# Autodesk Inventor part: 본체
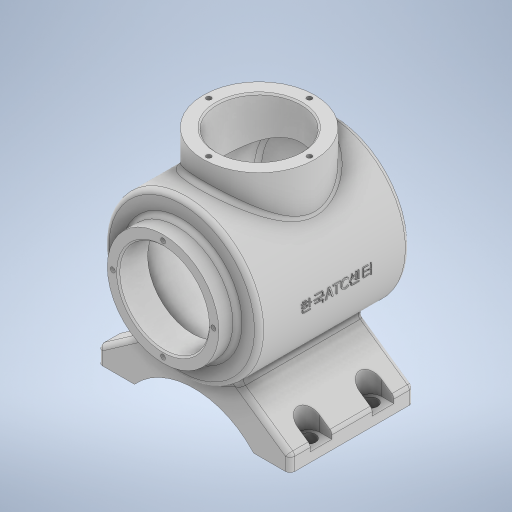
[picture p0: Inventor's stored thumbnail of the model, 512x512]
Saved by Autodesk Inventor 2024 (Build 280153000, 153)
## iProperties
Created: 2023-08
Part Number: 본체
Material: 일반
Document SubType Name: Modeling
Designer: Owner
Density: 1 g/cm^3
Appearance: 기본값
Mass: 474.432 g
Surface Area: 1056.17 cm^2
Volume: 474.432 cm^3
Author: Owner
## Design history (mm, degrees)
sketch "스케치1"
  geometry: L1 (0, 60)-(0, -60); L2 (0, -60)-(0, -8.872); L3 (29, 60)-(36, 60); L4 (36, 60)-(36, 48); L5 (36, 48)-(50, 48); L6 (50, 48)-(50, -48.336); L7 (43, -43.887)-(43, 41); L8 (43, 41)-(29, 41); L9 (29, 41)-(29, 60); A1 r 113 centre (0, 53) between (0, -60) and (50, -48.336); A2 r 106 centre (0, 53) between (0, -53) and (43, -43.887); 2 further points
  constraints: 18 end point, 4 perpendicular, 4 point on circle, 2 centre point, 2 point on line, 2 vertical, 1 coincident, 1 horizontal, 1 horizontal alignment, 1 midpoint, 1 vertical alignment, 2 other
  dimensions: "d1" = 120 distance of L1.start L1.end; "d2" = 113 radius of A1; "d3" = 100 diameter of L6 L1; "d4" = 72 diameter of L4 L1; "d5" = 12 distance of L3.end L4.end; "d6" = 7 radial gap between concentric circles of A1 A2; "d7" = 86 diameter of L7 L1; "d80" = 19 distance of L8.end L3.start (derived)
revolve "회전1" sketch "스케치1" stored, may be unused: angle "d8" = 90 deg
fillet "모깎기1" dims "d9" = 3
node "작업 평면1"
sketch "스케치2"
  geometry: L1 (-36, 60)-(36, 60) reference; C1 r 36 at (0, -2); 1 further point
  constraints: 1 centre point, 1 vertical alignment
  dimensions: "d11" = 72 diameter of C1; "d12" = 62 distance from line of L1 C1.centre
extrude "돌출1" join sketch "스케치2" stored distance "d13" = 10; taper "d14" = 0 deg
sketch "스케치3"
  geometry: L1 (36, -62)-(-36, -62) reference; C1 r 36 at (0, 0) reference; 2 further points
  dimensions: "d15" = 62 distance from line of L1 point (-32.5, 0); "d16" = 32.5 distance of C1.centre point (-32.5, 0)
hole "구멍1" sketch "스케치3" at (-32.5, 0) diameter "d17" = 3.242; stored, may be unused: countersink angle "d21" = 90 deg, drill point angle "d23" = 118 deg; dims "d18" = 8, "d19" = 4, "d20" = 2, "d22" = 10
sketch "스케치4"
  geometry: C1 r 36 at (0, 0) reference; 2 further points
  constraints: 1 coincident
hole "구멍2" sketch "스케치4" at (0, 0) diameter "d24" = 54; stored, may be unused: countersink angle "d28" = 90 deg, drill point angle "d30" = 0 deg; dims "d25" = 8, "d26" = 4, "d27" = 2, "d29" = 10
chamfer "모따기1" distance "d34" = 1; stored, may be unused: second distance "d35" = 2, angle "d36" = 45 deg
fillet "모깎기2" dims "d37" = 3
sketch "스케치5"
  geometry: L1 (-62, -77)-(-62, -67); L2 (62, -77)-(62, -67); L3 (-62, -77)-(-38.5, -77); L4 (62, -77)-(38.5, -77); L5 (-62, -67)-(-26.694, -42.278); L6 (62, -67)-(26.694, -42.278); A1 r 50 centre (0, 0) between (-26.694, -42.278) and (26.694, -42.278) reference; A2 r 52.096 centre (0, -112.096) between (38.5, -77) and (-38.5, -77); 2 further points
  constraints: 12 end point, 5 point on circle, 2 equal length, 2 horizontal, 2 vertical, 1 centre point, 1 vertical alignment
  dimensions: "d38" = 17 vertical distance of L4.end point (0, -60); "d39" = 77 vertical distance of L2.start point (0, 0); "d40" = 77 vertical distance of L1.start point (0, 0); "d41" = 77 distance of L4.end L3.end; "d43" = 10 distance of L2.start L2.end; "d45" = 124 distance of L2.end L1.end; "d46" = 55 deg angle of L1 L5; "d47" = 55 deg angle of L2 L6
extrude "돌출2" join sketch "스케치5" stored distance "d48" = 80; taper "d49" = 0 deg
node "작업 평면2"
sketch "스케치6"
  geometry: L1 (23.5, -80)-(0, -80) reference; L2 (23.5, -80)-(23.5, 0) reference; L3 (15.5, -67)-(23.5, -67); L4 (15.5, -53)-(23.5, -53); A1 r 7 centre (15.5, -60) between (15.5, -67) and (15.5, -53); 1 further point
  constraints: 4 end point, 2 perpendicular, 2 point on circle, 2 point on line, 2 tangent, 1 centre point
  dimensions: "d51" = 14 diameter of A1; "d52" = 20 distance from line of L1 A1.centre; "d53" = 8 distance from line of L2 A1.centre
extrude "돌출3" cut sketch "스케치6" distance "d54" = 50; taper "d55" = 0 deg
sketch "스케치7"
  geometry: A1 r 7 centre (15.5, 60) between (15.5, 67) and (15.5, 53) reference; 2 further points
  constraints: 1 coincident
hole "구멍3" sketch "스케치7" at (15.5, 60) diameter "d56" = 9; stored, may be unused: countersink angle "d60" = 90 deg, drill point angle "d62" = 0 deg; dims "d57" = 6, "d58" = 4, "d59" = 2, "d61" = 8
sketch "스케치8"
  geometry: 2 further points
  constraints: 1 vertical alignment
  dimensions: "d66" = 32.5 distance of point (0, 0) point (0, 32.5)
hole "구멍4" sketch "스케치8" at (0, 32.5) diameter "d67" = 3.242; stored, may be unused: countersink angle "d71" = 90 deg, drill point angle "d73" = 118 deg; dims "d68" = 8, "d69" = 4, "d70" = 2, "d72" = 10
fillet "모깎기3" dims "d74" = 3
fillet "모깎기4" dims "d75" = 3
fillet "모깎기5" dims "d76" = 3
node "작업 평면3"
sketch "스케치9"
  geometry: L1 (-36, 60.168)-(36, 60.168) reference; 3 further points
  constraints: 1 midpoint, 1 vertical alignment, 1 other
  dimensions: "d81" = 62 distance from line of L1 point (0, -1.832)
feature "엠보싱1" sketch "스케치9" dims "d1" = 120, "d2" = 113, "d3" = 100, "d4" = 72, "d5" = 12, "d6" = 7, "d7" = 86, "d80" = 19 (derived), "d82" = 0.5, "d83" = 0
feature "ʻ耀ʽ耀ʿ耀ˁ耀˃耀˅耀ˇ耀ˉ耀" dims "d1" = 120, "d2" = 113, "d3" = 100, "d4" = 72, "d5" = 12, "d6" = 7, "d7" = 86, "d8" = 90 deg, "d9" = 3, "d10" = 65, "d11" = 72, "d12" = 62, "d13" = 10, "d14" = 0, "d15" = 62, "d16" = 32.5, "d17" = 3.242, "d18" = 8, "d19" = 4, "d20" = 2, "d21" = 90 deg, "d22" = 10, "d23" = 118 deg, "d24" = 54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
node "솔리드1"
pattern_circular "원형 패턴1" dims angle "d32" = 360 deg
pattern_linear "직사각형 패턴1" dims "d65" = 40
mirror "미러1"
pattern_circular "원형 패턴2" dims angle "d78" = 360 deg
feature "A9D066F2-1C7D-4E18-AEED-F7BC21143FA4" dims "d56" = 9, "d57" = 6, "d58" = 4, "d59" = 2, "d60" = 90 deg, "d61" = 8, "d62" = 0
